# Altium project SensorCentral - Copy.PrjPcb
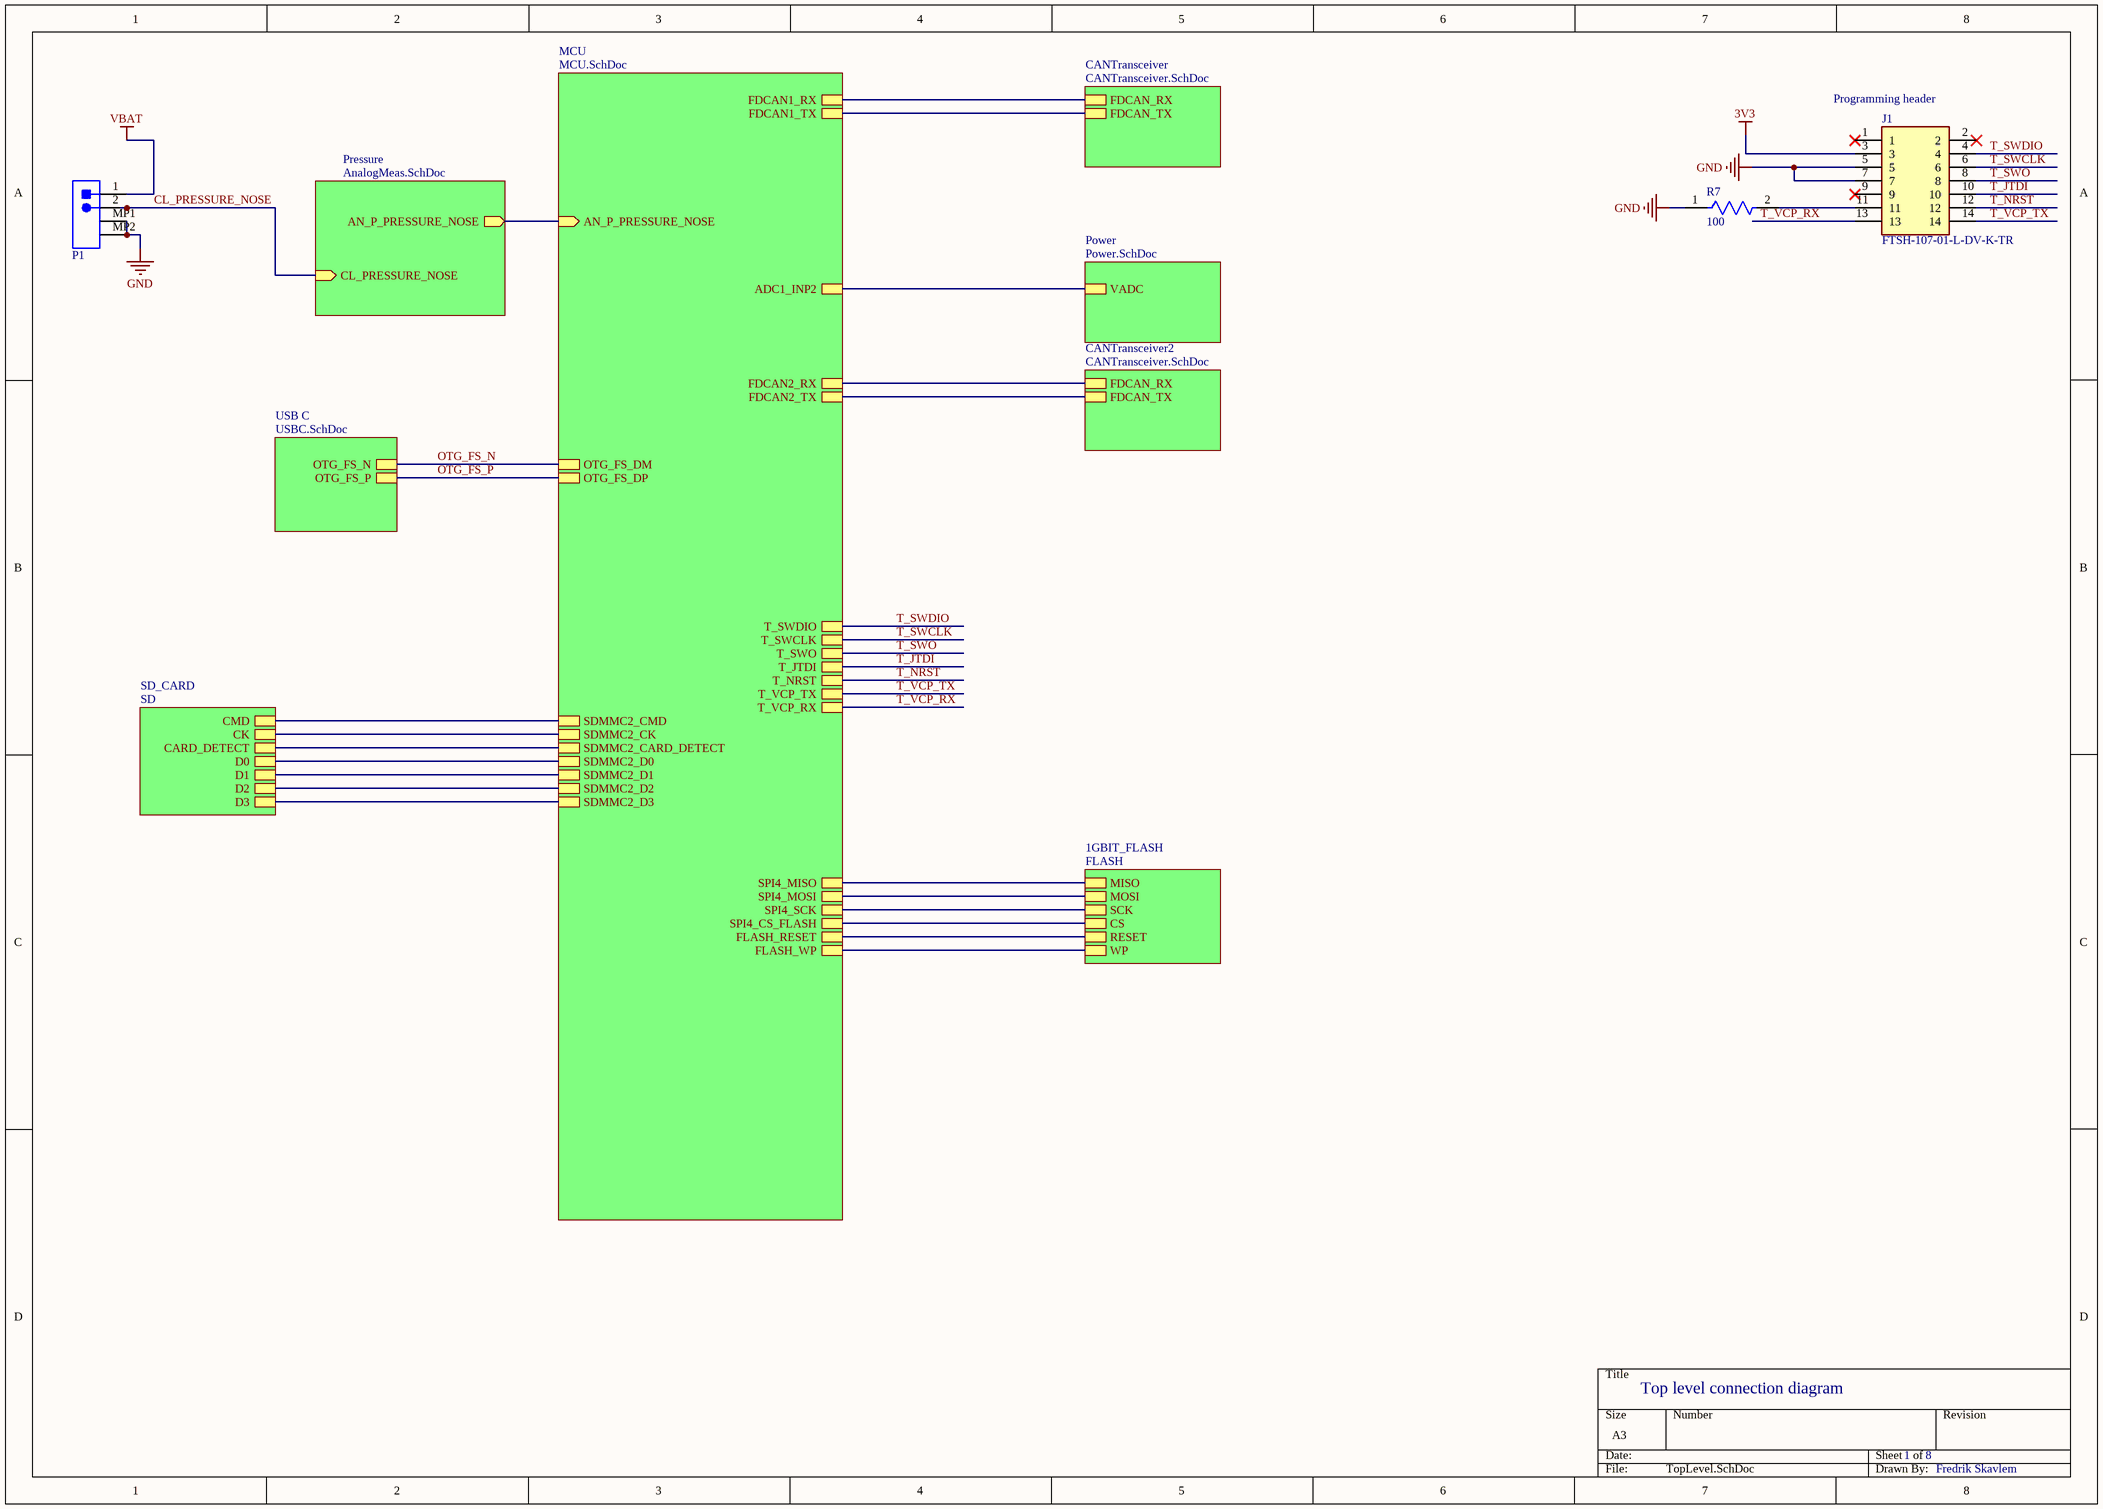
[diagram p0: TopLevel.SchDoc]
CAGE_CODE: ?????; CONTRACT_NUMBER: <CONTRACT NO>; DOC_NO_ASSY_DWG: <ASSY DWG NO>; DOC_NO_BOM: <BOM DOC NO>; DOC_NO_FAB_DWG: <FAB DWG NO>; DOC_NO_SCH_DWG: <SCH DWG NO>; PCB_2_DEC_TOL: +/-.01; PCB_3_DEC_TOL: +/-.010; PCB_ANG_TOL: +/-1/2; PCB_ASSEMBLY_NO: <PCB ASSY NO>; PCB_CHECKER: - -----; PCB_CHECKER_APP_DATE: --/--/----; PCB_DESIGNER: - -----; PCB_DESIGNER_APP_DATE: --/--/----; PCB_DWG_NO: <PCB DWG NO>; PCB_ENGINEER: - -----; PCB_ENGINEER_APP_DATE: --/--/----; PCB_PART_NUMBER: <PCB PN>; PCB_REV: A; SCH_REV: A
8 sheets, 91 parts. Net scope: hierarchical (ports join the sheet entries above them; power ports are global).
Board file: SensorCentral.PcbDoc
Sheets:
  TopLevel.SchDoc
    MCU = MCU.SchDoc
    Power = Power.SchDoc
    CANTransceiver = CANTransceiver.SchDoc
    SD_CARD = SD.SchDoc
    1GBIT_FLASH = Flash.SchDoc
    CANTransceiver2 = CANTransceiver.SchDoc
    Pressure = AnalogMeas.SchDoc
    USB C = USBC.SchDoc

## Sheet TopLevel.SchDoc
size A3; DrawnBy: Fredrik Skavlem; SheetNumber: 1; SheetTotal: 8

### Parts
J1  FTSH-107-01-L-DV-K-TR  [FTSH10701LDVKTR]
P1  S2B-PH-SM4-TB(LF)(SN)  [JST- S2B-PH-SM4-TB(LF)(SN)-2_V]  (value not drawn)
R7  100  [FP-RT0603-MFG]

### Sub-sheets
1GBIT_FLASH = FLASH: WP, RESET, CS, SCK, MOSI, MISO
CANTransceiver = CANTransceiver.SchDoc: FDCAN_RX, FDCAN_TX
CANTransceiver2 = CANTransceiver.SchDoc: FDCAN_RX, FDCAN_TX
MCU = MCU.SchDoc: FDCAN1_RX, FDCAN1_TX, T_SWDIO, T_SWCLK, T_SWO, T_JTDI, T_NRST, T_VCP_TX, T_VCP_RX, SPI4_MISO, SPI4_MOSI, SPI4_SCK, FLASH_RESET, SPI4_CS_FLASH, FLASH_WP, SDMMC2_CMD, SDMMC2_CK, SDMMC2_D0, SDMMC2_D1, SDMMC2_D2, SDMMC2_D3, SDMMC2_CARD_DETECT, ADC1_INP2, FDCAN2_RX, FDCAN2_TX, AN_P_PRESSURE_NOSE (in), OTG_FS_DM, OTG_FS_DP
Power = Power.SchDoc: VADC
Pressure = AnalogMeas.SchDoc: AN_P_PRESSURE_NOSE (out), CL_PRESSURE_NOSE (in)
SD_CARD = SD: CMD, CK, CARD_DETECT, D0, D1, D2, D3
USB C = USBC.SchDoc: OTG_FS_N, OTG_FS_P

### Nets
3V3: J1.3  [project net VDD]
GND: J1.5 J1.7 P1.MP1 P1.MP2 R7.1
VBAT: P1.1
ADC1_INP2: sheet MCU/ADC1_INP2, sheet Power/VADC
AN_P_PRESSURE_NOSE: sheet MCU/AN_P_PRESSURE_NOSE, sheet Pressure/AN_P_PRESSURE_NOSE
CARD_DETECT: sheet MCU/SDMMC2_CARD_DETECT, sheet SD_CARD/CARD_DETECT
CD/DAT3: sheet MCU/SDMMC2_D3, sheet SD_CARD/D3
CL_PRESSURE_NOSE: P1.2 ; sheet Pressure/CL_PRESSURE_NOSE
CLK: sheet MCU/SDMMC2_CK, sheet SD_CARD/CK
CMD: sheet MCU/SDMMC2_CMD, sheet SD_CARD/CMD
CS: sheet MCU/SPI4_CS_FLASH, sheet 1GBIT_FLASH/CS
DAT0: sheet MCU/SDMMC2_D0, sheet SD_CARD/D0
DAT1: sheet MCU/SDMMC2_D1, sheet SD_CARD/D1
DAT2: sheet MCU/SDMMC2_D2, sheet SD_CARD/D2
FDCAN1_RX: sheet MCU/FDCAN1_RX, sheet CANTransceiver/FDCAN_RX
FDCAN1_TX: sheet MCU/FDCAN1_TX, sheet CANTransceiver/FDCAN_TX
FDCAN2_RX: sheet MCU/FDCAN2_RX, sheet CANTransceiver2/FDCAN_RX
FDCAN2_TX: sheet MCU/FDCAN2_TX, sheet CANTransceiver2/FDCAN_TX
FLASH_RESET: sheet MCU/FLASH_RESET, sheet 1GBIT_FLASH/RESET
FLASH_WP: sheet MCU/FLASH_WP, sheet 1GBIT_FLASH/WP
MISO: sheet MCU/SPI4_MISO, sheet 1GBIT_FLASH/MISO
MOSI: sheet MCU/SPI4_MOSI, sheet 1GBIT_FLASH/MOSI
OTG_FS_N: sheet MCU/OTG_FS_DM, sheet USB C/OTG_FS_N
OTG_FS_P: sheet MCU/OTG_FS_DP, sheet USB C/OTG_FS_P
SCK: sheet MCU/SPI4_SCK, sheet 1GBIT_FLASH/SCK
T_JTDI: J1.10 ; sheet MCU/T_JTDI
T_NRST: J1.12 ; sheet MCU/T_NRST
T_SWCLK: J1.6 ; sheet MCU/T_SWCLK
T_SWDIO: J1.4 ; sheet MCU/T_SWDIO
T_SWO: J1.8 ; sheet MCU/T_SWO
T_VCP_RX: J1.13 ; sheet MCU/T_VCP_RX
T_VCP_TX: J1.14 ; sheet MCU/T_VCP_TX
NetJ1_11: J1.11 R7.2

Not connected (* = marked no-connect by the designer): J1 1* 2* 9*

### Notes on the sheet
- (near J1) Programming header
- Top level connection diagram
- 1
- 8
- Fredrik Skavlem

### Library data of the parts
J1 = FTSH-107-01-L-DV-K-TR: Connector; Manufacturer_Name: SAMTEC
P1 = CMP-002-00031-2: Male Header, Pitch 2 mm, 1 x 2 Position, Height 5.5 mm, -25 to 85 degC, RoHS, Tape and Reel; Manufacturer: JST
R7 = CMP-03412-030646-1: RT0603 100Ω 0.1W 50 ppm/°C 1.00% RT0603FRE07100RL; Manufacturer: Yageo; Manufacturer Part Number: RT0603FRE10100RL; Tolerance: 0.01; Voltage Rating: 75V

## Sheet MCU.SchDoc
size A3; ENG_APP_DATE: --/--/--; DSN_APP_DATE: --/--/--; CHK_APP_DATE: --/--/--; SheetNumber: 2; SheetTotal: 8
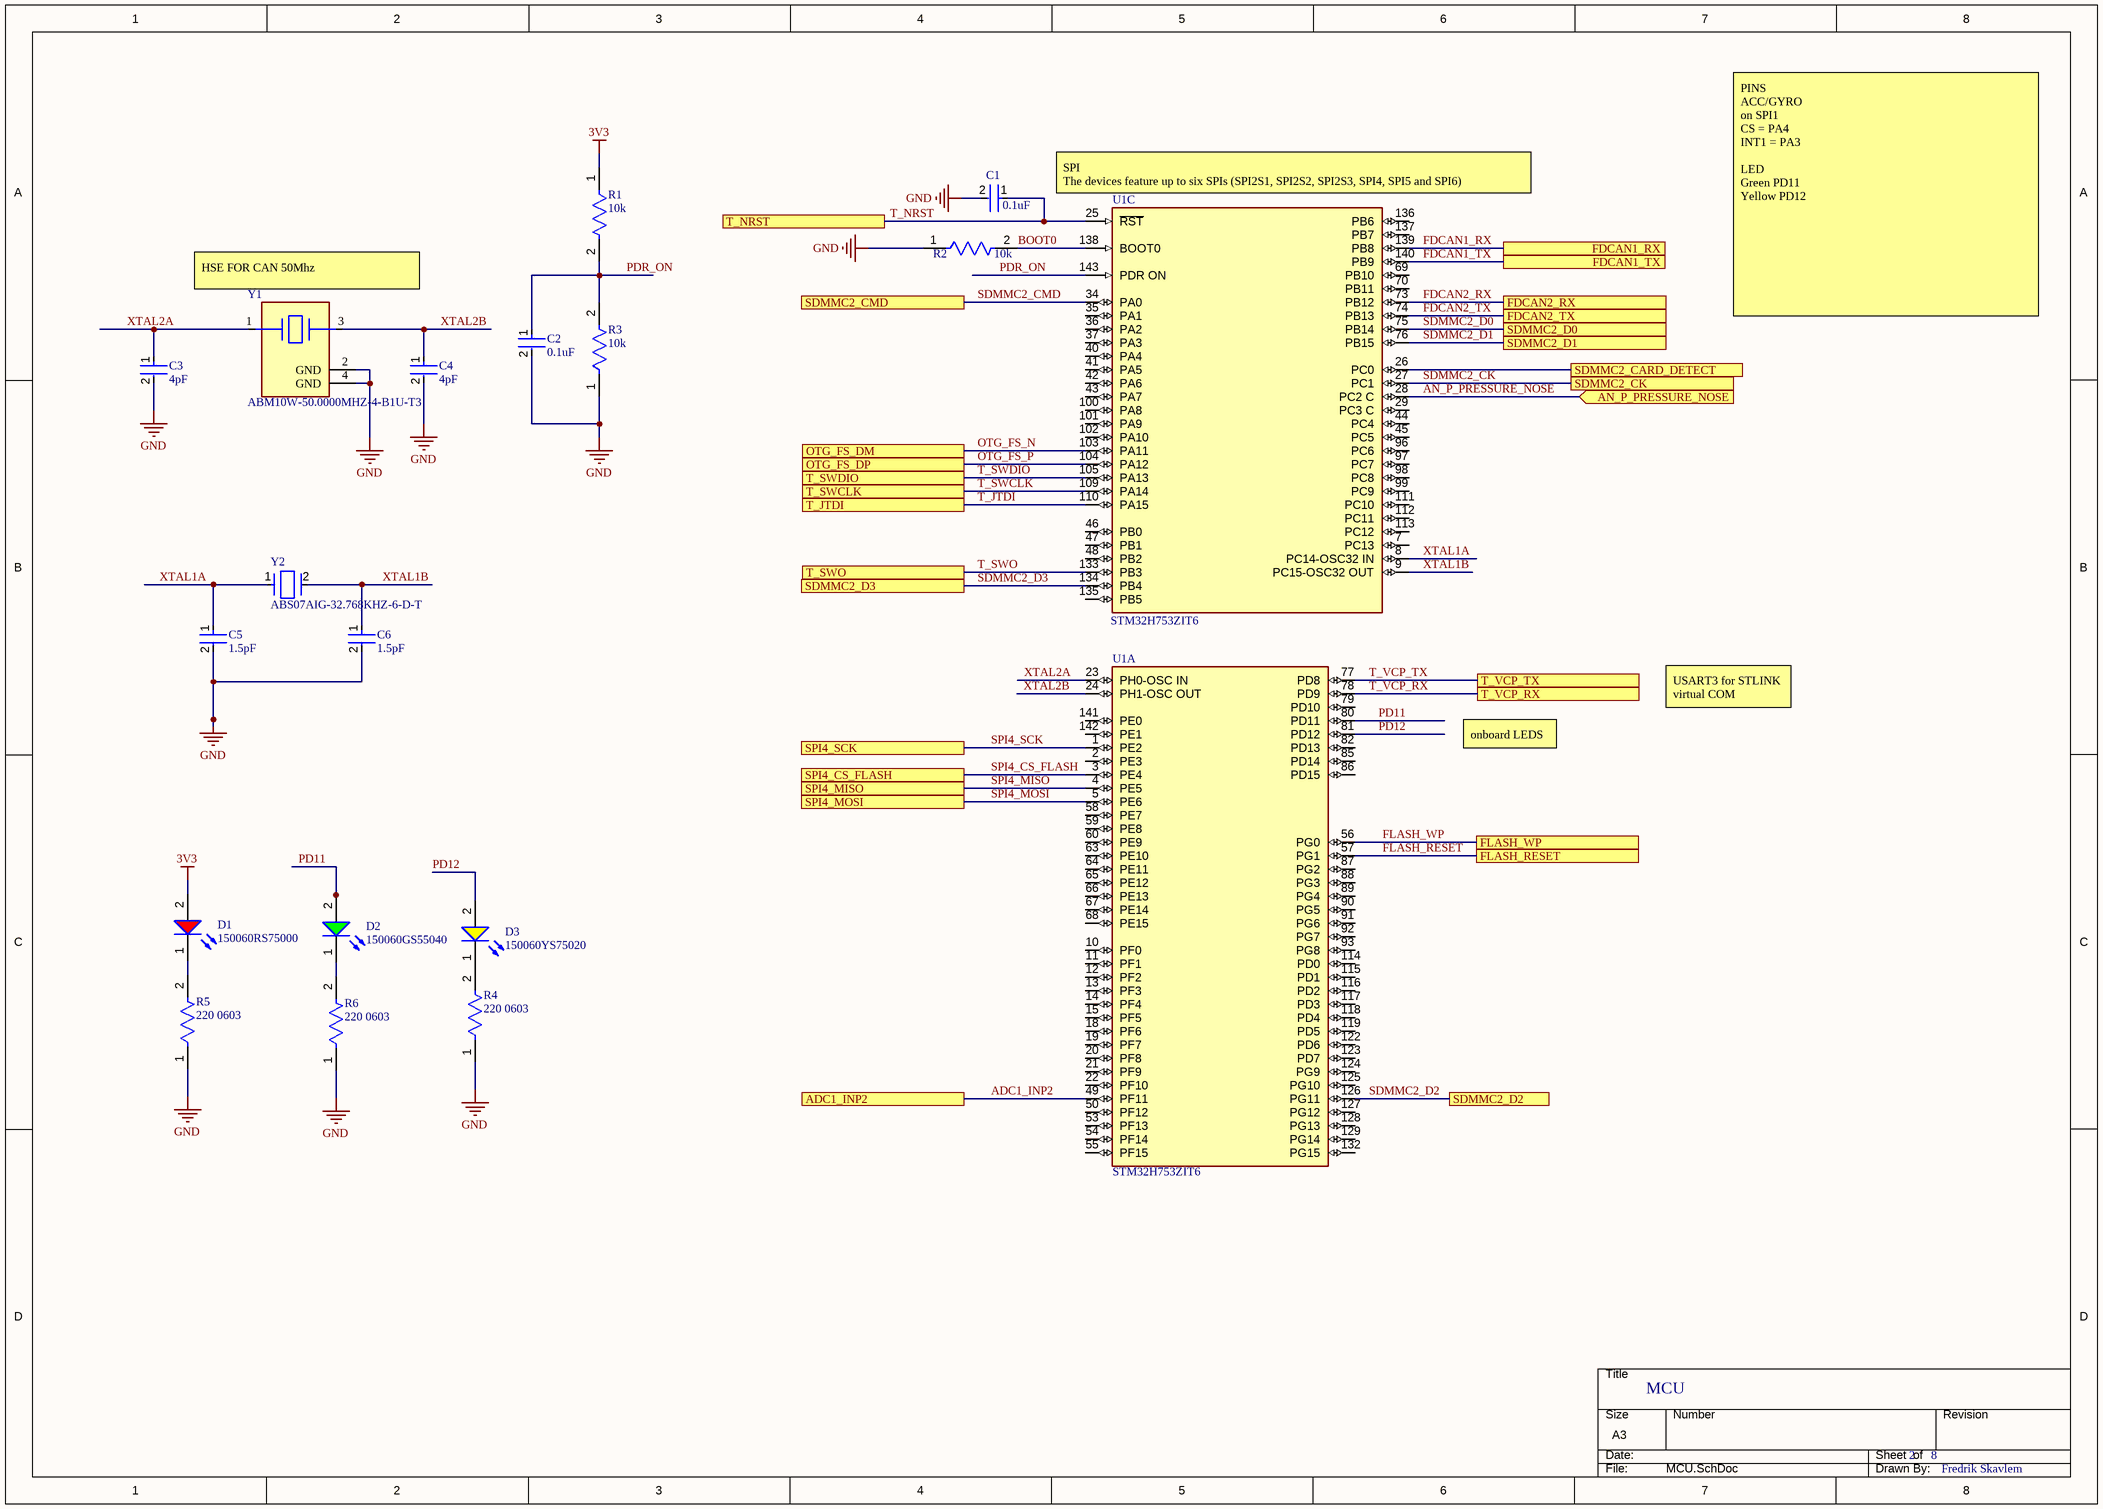
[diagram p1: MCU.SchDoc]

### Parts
C1  0.1uF  [FP-CL10-IPC_C]
C2  0.1uF  [FP-CL10-IPC_C]
C3  4pF  [FP-GQM187-0_15-IPC_B]
C4  4pF  [FP-GQM187-0_15-IPC_B]
C5  1.5pF  [FP-C0603C-CF-IPC_C]
C6  1.5pF  [FP-C0603C-CF-MFG]
D1  150060RS75000  [WL-SMCW_0603_150060xx75000]
D2  150060GS55040  [WL-SMCD_0603]
D3  150060YS75020  [WL-SMCW_0603_150060xx75020]
R1  10k  [FP-RT0603-IPC_C]
R2  10k  [FP-RT0603-IPC_C]
R3  10k  [FP-RT0603-IPC_C]
R4  220 0603  [FP-AF0603-IPC_C]
R5  220 0603  [FP-AF0603-IPC_C]
R6  220 0603  [FP-AF0603-IPC_C]
U1  STM32H753ZIT6  [FP-LQFP144-1A-MFG]  (parts A,C of 3)
Y1  ABM10W-50.0000MHZ-4-B1U-T3  [FP-ABM10W-MFG]
Y2  ABS07AIG-32.768KHZ-6-D-T  [FP-ABS07AIG-MFG]

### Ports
ADC1_INP2, AN_P_PRESSURE_NOSE (in), FDCAN1_RX, FDCAN1_TX, FDCAN2_RX, FDCAN2_TX, FLASH_RESET, FLASH_WP, OTG_FS_DM, OTG_FS_DP, SDMMC2_CARD_DETECT, SDMMC2_CK, SDMMC2_CMD, SDMMC2_D0, SDMMC2_D1, SDMMC2_D2, SDMMC2_D3, SPI4_CS_FLASH, SPI4_MISO, SPI4_MOSI, SPI4_SCK, T_JTDI, T_NRST, T_SWCLK, T_SWDIO, T_SWO, T_VCP_RX, T_VCP_TX

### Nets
3V3: D1.2(A) R1.1  [project net VDD]
GND: C1.2 C2.2 C3.2 C4.2 C5.2 C6.2 R2.1 R3.1 R4.1 R5.1 R6.1 Y1.2(GND) Y1.4(GND)
ADC1_INP2: U1.49(PF11) ; port ADC1_INP2
AN_P_PRESSURE_NOSE: U1.28(PC2_C) ; port AN_P_PRESSURE_NOSE
BOOT0: R2.2 U1.138(BOOT0)
CARD_DETECT: U1.26(PC0) ; port SDMMC2_CARD_DETECT
FDCAN1_RX: U1.139(PB8) ; port FDCAN1_RX
FDCAN1_TX: U1.140(PB9) ; port FDCAN1_TX
FDCAN2_RX: U1.73(PB12) ; port FDCAN2_RX
FDCAN2_TX: U1.74(PB13) ; port FDCAN2_TX
FLASH_RESET: U1.57(PG1) ; port FLASH_RESET
FLASH_WP: U1.56(PG0) ; port FLASH_WP
OTG_FS_N: U1.103(PA11) ; port OTG_FS_DM
OTG_FS_P: U1.104(PA12) ; port OTG_FS_DP
PD11: D2.2(A) U1.80(PD11)
PD12: D3.2(A) U1.81(PD12)
PDR_ON: C2.1 R1.2 R3.2 U1.143(PDR_ON)
SDMMC2_CK: U1.27(PC1) ; port SDMMC2_CK  [project net CLK]
SDMMC2_CMD: U1.34(PA0) ; port SDMMC2_CMD  [project net CMD]
SDMMC2_D0: U1.75(PB14) ; port SDMMC2_D0  [project net DAT0]
SDMMC2_D1: U1.76(PB15) ; port SDMMC2_D1  [project net DAT1]
SDMMC2_D2: U1.126(PG11) ; port SDMMC2_D2  [project net DAT2]
SDMMC2_D3: U1.134(PB4) ; port SDMMC2_D3  [project net CD/DAT3]
SPI4_CS_FLASH: U1.3(PE4) ; port SPI4_CS_FLASH  [project net CS]
SPI4_MISO: U1.4(PE5) ; port SPI4_MISO  [project net MISO]
SPI4_MOSI: U1.5(PE6) ; port SPI4_MOSI  [project net MOSI]
SPI4_SCK: U1.1(PE2) ; port SPI4_SCK  [project net SCK]
T_JTDI: U1.110(PA15) ; port T_JTDI
T_NRST: C1.1 U1.25(~{RST}) ; port T_NRST
T_SWCLK: U1.109(PA14) ; port T_SWCLK
T_SWDIO: U1.105(PA13) ; port T_SWDIO
T_SWO: U1.133(PB3) ; port T_SWO
T_VCP_RX: U1.78(PD9) ; port T_VCP_RX
T_VCP_TX: U1.77(PD8) ; port T_VCP_TX
XTAL1A: C5.1 U1.8(PC14-OSC32_IN) Y2.1
XTAL1B: C6.1 U1.9(PC15-OSC32_OUT) Y2.2
XTAL2A: C3.1 U1.23(PH0-OSC_IN) Y1.1
XTAL2B: C4.1 U1.24(PH1-OSC_OUT) Y1.3
NetD1_1: D1.1(K) R5.2
NetD2_1: D2.1(K) R6.2
NetD3_1: D3.1(K) R4.2

Not connected (* = marked no-connect by the designer): U1 2(PE3) 7(PC13) 10(PF0) 11(PF1) 12(PF2) 13(PF3) 14(PF4) 15(PF5) 18(PF6) 19(PF7) 20(PF8) 21(PF9) 22(PF10) 29(PC3_C) 35(PA1) 36(PA2) 37(PA3) 40(PA4) 41(PA5) 42(PA6) 43(PA7) 44(PC4) 45(PC5) 46(PB0) 47(PB1) 48(PB2) 50(PF12) 53(PF13) 54(PF14) 55(PF15) 58(PE7) 59(PE8) 60(PE9) 63(PE10) 64(PE11) 65(PE12) 66(PE13) 67(PE14) 68(PE15) 69(PB10) 70(PB11) 79(PD10) 82(PD13) 85(PD14) 86(PD15) 87(PG2) 88(PG3) 89(PG4) 90(PG5) 91(PG6) 92(PG7) 93(PG8) 96(PC6) 97(PC7) 98(PC8) 99(PC9) 100(PA8) 101(PA9) 102(PA10) 111(PC10) 112(PC11) 113(PC12) 114(PD0) 115(PD1) 116(PD2) 117(PD3) 118(PD4) 119(PD5) 122(PD6) 123(PD7) 124(PG9) 125(PG10) 127(PG12) 128(PG13) 129(PG14) 132(PG15) 135(PB5) 136(PB6) 137(PB7) 141(PE0) 142(PE1)

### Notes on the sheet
- (near U1) SPI
  The devices feature up to six SPIs (SPI2S1, SPI2S2, SPI2S3, SPI4, SPI5 and SPI6)
- (near Y1) HSE FOR CAN 50Mhz
- PINS
  ACC/GYRO
  on SPI1
  CS = PA4
  INT1 = PA3
  LED
  Green PD11
  Yellow PD12
- USART3 for STLINK virtual COM
- onboard LEDS
- MCU
- 2
- 8
- Fredrik Skavlem

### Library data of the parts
C1 C2 = CMP-13271-002683-1: Cap Ceramic 100nF 16V X7R ±10% Pad SMD 0603 +125°C T/R / CL10B104KO8WPNC
C3 C4 = CMP-06035-061124-1: GQM1875C2E4R0BB12D / Ceramic Capacitor 4pF ±0.1pF 250VDC C0G 0603 Paper T/R; Voltage Rating: 250V
C5 C6 = CMP-03020-023157-1: C0603 1.5 pF X8R 30ppm/°C 0.1 pF 25 V / C0603C159B3HACTU; Manufacturer: KEMET; Automotive Grade: Grade 1; Material: Ceramic; Tolerance: 0.1 pF; Voltage Rating: 25 V
D1 = CMP-1426-00001-3: NexarPartId: 29717776; Color: Red; Power Dissipation: 72mW; Max Reverse Voltage (DC): 5V; Peak Wavelength: 630nm; Viewing Angle: 140°; Forward Voltage: 2V; Luminous Intensity: 250mcd; Forward Current: 100mA; Dominant Wavelength: 625nm; Lens Style: Clear, Rectangular; Max Junction Temperature (Tj): 95°C; Test Current: 20mA
D2 = CMP-03913-90235563-2: 150060GS55040 WL-SMCD SMT Mono-color Chip LED Diffused; Forward Voltage: 3.2V; Forward Current: 60mA; Luminous Intensity: 430mcd; Peak Wavelength: 520nm; Viewing Angle: 140°; Wavelength: 525nm; Max Reverse Voltage (DC): 5V
D3 = CMP-03913-104891429-2: WL-SMCW SMT Mono-Color Chip LED Waterclear super f; Forward Voltage: 2V; Forward Current: 60mA; Max Reverse Voltage (DC): 5V; Peak Wavelength: 595nm; Viewing Angle: 140°; Dominant Wavelength: 590nm; Luminous Intensity: 130mcd
R1-R3 = CMP-03412-005349-1: RES SMD 10K OHM 1% 1/10W 0603 / RT0603FRE0710KL; Manufacturer: Yageo; Value: 10KΩ; Temperature Coefficient: 50 ppm/°C; Power Rating: 0.1W; Tolerance: 0.01; Voltage Rating: 75V
R4-R6 = CMP-03412-038529-1: AF0603JR-07220RL Anti-Sulfurated Chip Resistors Automotive Grade 220Ω 5% 100ppm/°C 0603; Max Power Dissipation: 100mW; Resistance: 220R
U1 = CMP-12105-000009-1: LQFP 144 20X20X1.4 2; Manufacturer: STMicroelectronics; Number Of Pwm Channels: 24; Number Of I/Os: 114; Number Of Cores: 1; Min Supply Voltage: 1.62V; Interface: I2C,SPI,UART,USART,CAN,USB,LIN,IrDA,Ethernet,I2S,SMBus,Other; Standoff Height: 0.05mm; Number Of I2C Channels: 4; Max Junction Temp: +125°C; Memory Type: FLASH; Ram Size: 1MBytes; Number Of Spi Channels: 6; Core Architecture: ARM Cortex-M7; Number Of Uart Channels: 9; Memory Size: 2MBytes; Number Of Adc Channels: 36; Frequency: 480MHz; Data Bus Width: 32bits; Max Supply Voltage: 3.6V; Number Of Usb Channels: 2; Number Of A/D Converters: 3; Number Of Timers/Counters: 20
Y1 = CMP-27762-007472-1: Crystal 50MHz ±10ppm 4pF SMD-4 2.5mm x 2mm; ESR (Equivalent Series Resistance): 70R
Y2 = CMP-27762-015953-1: Crystal 32.768kHz ±20ppm (Tol) 6pF FUND 70kΩ Automotive 2-Pin Mini-CSMD T/R; ESR (Equivalent Series Resistance): 70kR

## Sheet Power.SchDoc
size A3; SheetNumber: 4; SheetTotal: 8
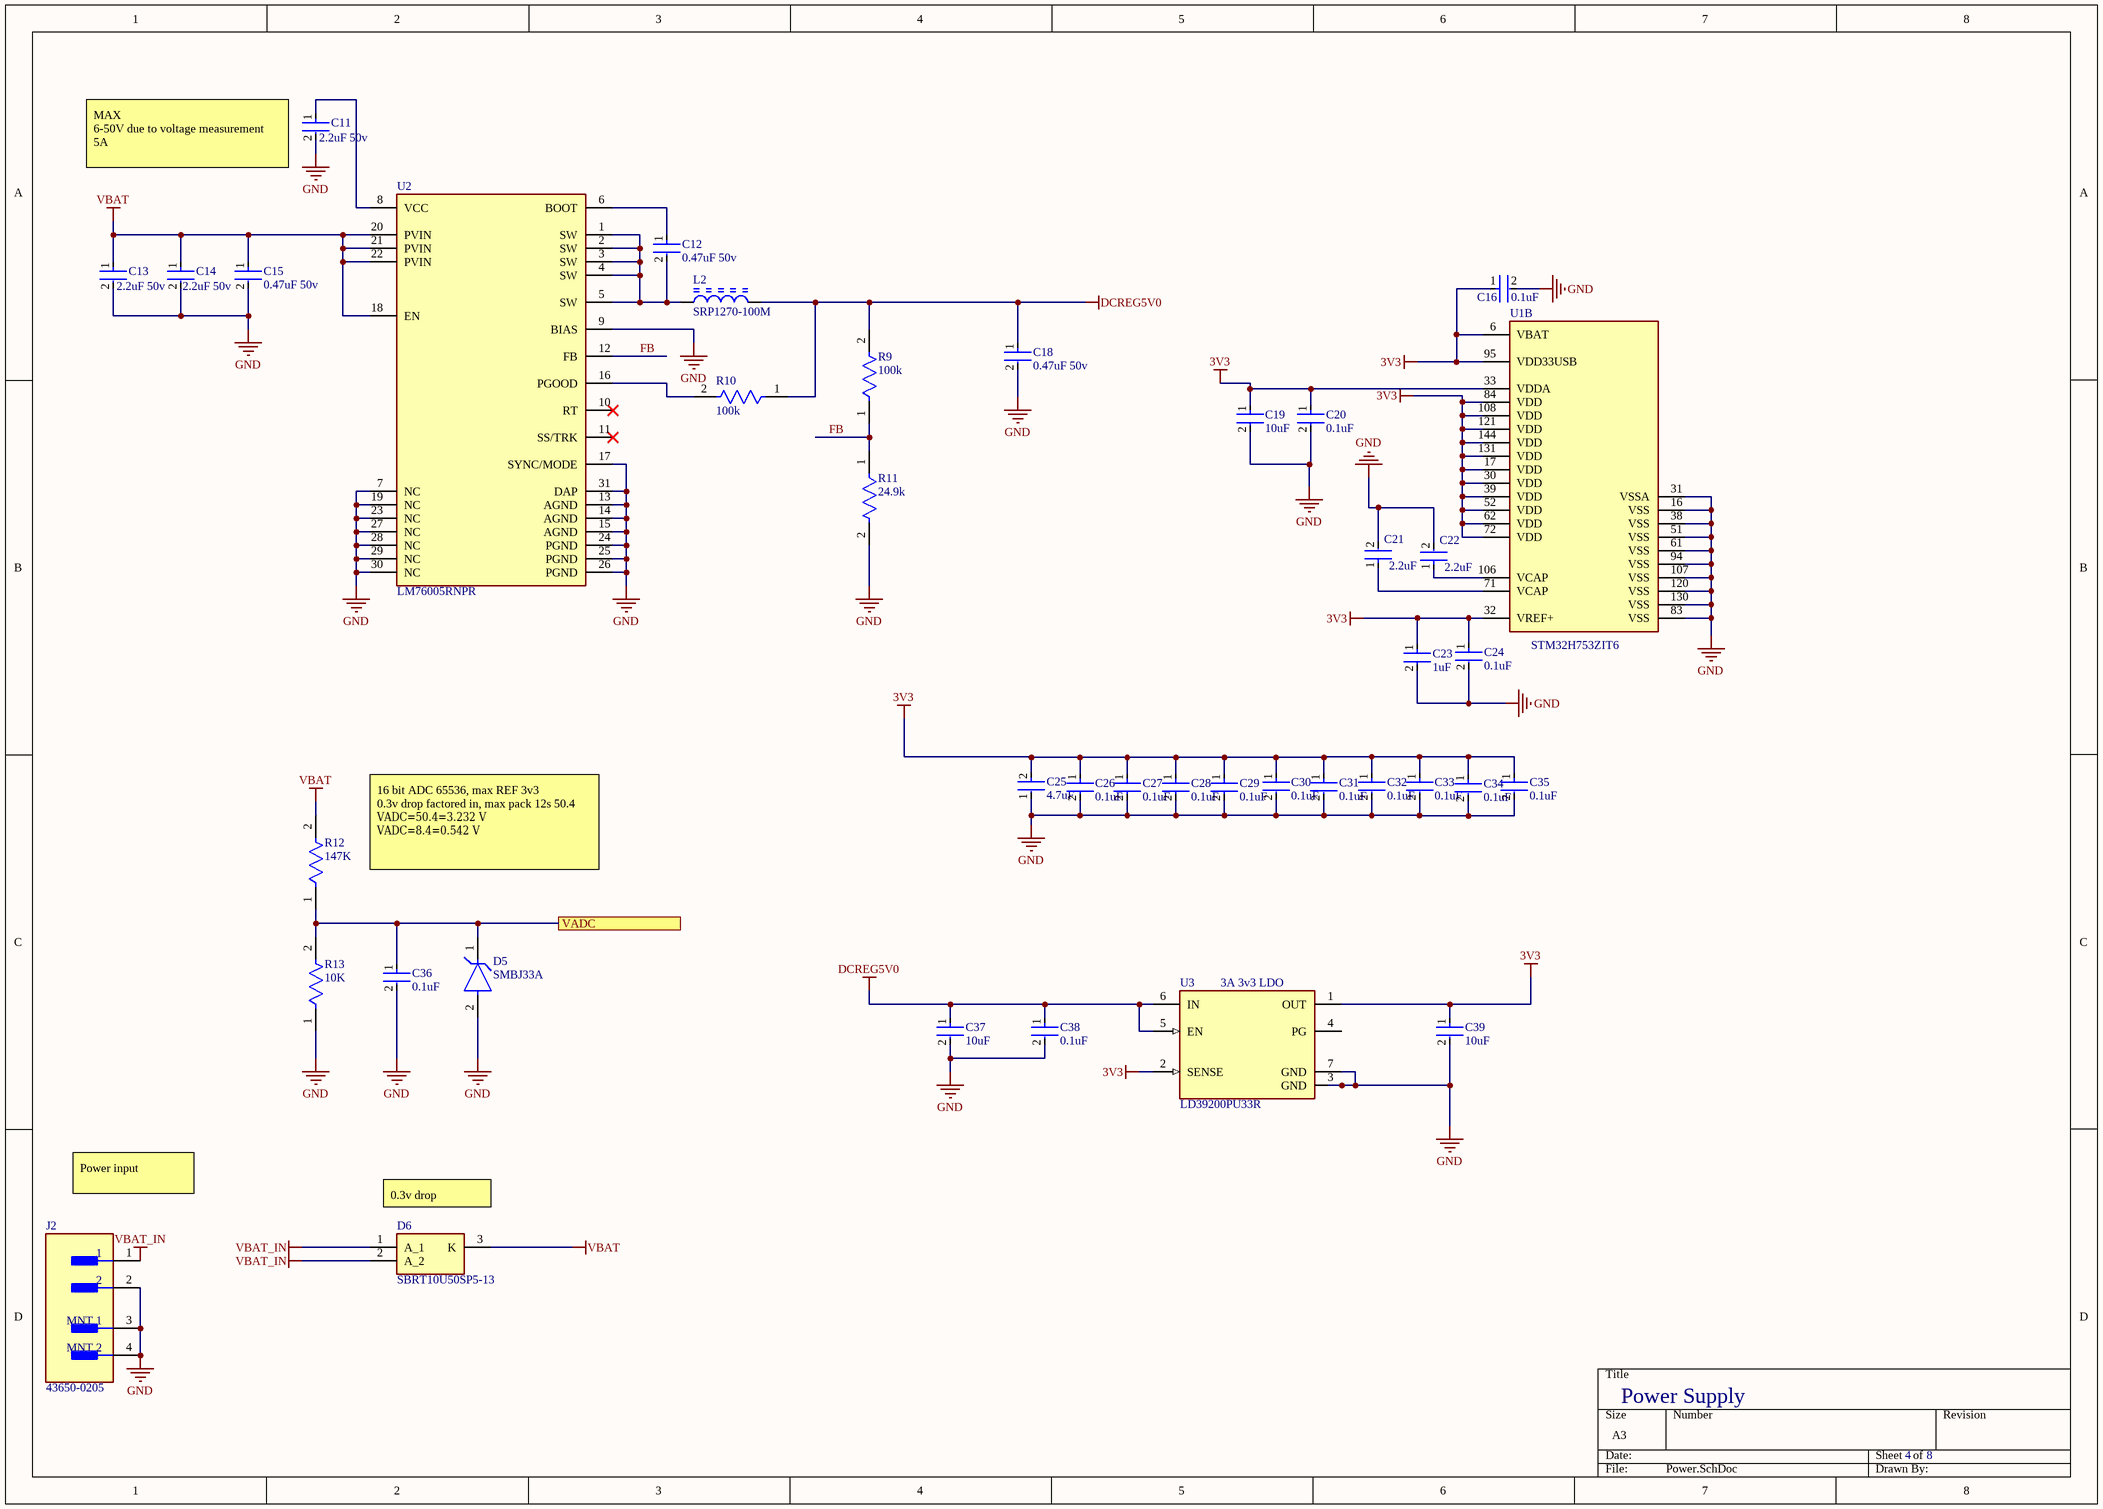
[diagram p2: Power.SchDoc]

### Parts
C11  2.2uF 50v  [FP-GRM188-0_2-IPC_C]
C12  0.47uF 50v  [FP-0603-L_1_6_0_15-W_0_8-MFG]
C13  2.2uF 50v  [FP-GRM188-0_2-IPC_C]
C14  2.2uF 50v  [FP-GRM188-0_2-IPC_C]
C15  0.47uF 50v  [FP-0603-L_1_6_0_15-W_0_8-MFG]
C16  0.1uF  [FP-CL10-IPC_C]
C18  0.47uF 50v  [FP-0603-L_1_6_0_15-W_0_8-MFG]
C19  10uF  [FP-CL10-IPC_C]
C20  0.1uF  [FP-CL10-IPC_C]
C21  2.2uF  [FP-CL10-IPC_C]
C22  2.2uF  [FP-CL10-IPC_C]
C23  1uF  [FP-CL10-IPC_C]
C24  0.1uF  [FP-CL10-IPC_C]
C25  4.7uF  [FP-C1608-080-0_1-MFG]
C26  0.1uF  [FP-CL10-IPC_C]
C27  0.1uF  [FP-CL10-IPC_C]
C28  0.1uF  [FP-CL10-IPC_C]
C29  0.1uF  [FP-CL10-IPC_C]
C30  0.1uF  [FP-CL10-IPC_C]
C31  0.1uF  [FP-CL10-IPC_C]
C32  0.1uF  [FP-CL10-IPC_C]
C33  0.1uF  [FP-CL10-IPC_C]
C34  0.1uF  [FP-CL10-IPC_C]
C35  0.1uF  [FP-CL10-IPC_C]
C36  0.1uF  [FP-CL10-IPC_C]
C37  10uF  [FP-CL10-IPC_C]
C38  0.1uF  [FP-CL10-IPC_C]
C39  10uF  [FP-CL10-IPC_C]
D5  SMBJ33A  [FP-SMBJ-MFG]
D6  SBRT10U50SP5-13  [SBRT10U50SP513]
J2  43650-0205  [FP-43650-0205-MFG]
L2  SRP1270-100M  [BOUR-SRP1270-100M-2_V]
R9  100k  [FP-RC0603-0_55-IPC_C]
R10  100k  [FP-RC0603-0_55-IPC_C]
R11  24.9k  [FP-RG1608-IPC_C]
R12  147K  [FP-RT0603-MFG]
R13  10K  [FP-ERJPB3-IPC_C]
U1  STM32H753ZIT6  [FP-LQFP144-1A-MFG]  (part B of 3)
U2  LM76005RNPR  [FP-RNP0030A-MFG]
U3  LD39200PU33R  [FP-DFN6-7946637-MFG]

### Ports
VADC

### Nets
3V3: C16.1 C19.1 C20.1 C23.1 C24.1 C25.2 C26.1 C27.1 C28.1 C29.1 C30.1 C31.1 C32.1 C33.1 C34.1 C35.1 C39.1 U1.6(VBAT) U1.17(VDD) U1.30(VDD) U1.32(VREF+) U1.33(VDDA) U1.39(VDD) U1.52(VDD) U1.62(VDD) U1.72(VDD) U1.84(VDD) U1.95(VDD33USB) U1.108(VDD) U1.121(VDD) U1.131(VDD) U1.144(VDD) U3.1(OUT) U3.2(SENSE)  [project net VDD]
DCREG5V0: C18.1 C37.1 C38.1 L2.2 R9.2 R10.1 U3.5(EN) U3.6(IN)
GND: C11.2 C13.2 C14.2 C15.2 C16.2 C18.2 C19.2 C20.2 C21.2 C22.2 C23.2 C24.2 C25.1 C26.2 C27.2 C28.2 C29.2 C30.2 C31.2 C32.2 C33.2 C34.2 C35.2 C36.2 C37.2 C38.2 C39.2 D5.2(A) J2.2 J2.3(MNT_1) J2.4(MNT_2) R11.2 R13.1 U1.16(VSS) U1.31(VSSA) U1.38(VSS) U1.51(VSS) U1.61(VSS) U1.83(VSS) U1.94(VSS) U1.107(VSS) U1.120(VSS) U1.130(VSS) U2.7(NC) U2.9(BIAS) U2.13(AGND) U2.14(AGND) U2.15(AGND) U2.17(SYNC/MODE) U2.19(NC) U2.23(NC) U2.24(PGND) U2.25(PGND) U2.26(PGND) U2.27(NC) U2.28(NC) U2.29(NC) U2.30(NC) U2.31(DAP) U3.3(GND) U3.7(GND)
VBAT: C13.1 C14.1 C15.1 D6.3(K) R12.2 U2.18(EN) U2.20(PVIN) U2.21(PVIN) U2.22(PVIN)
VBAT_IN: D6.1(A_1) D6.2(A_2) J2.1
ADC1_INP2: C36.1 D5.1(C) R12.1 R13.2 ; port VADC
FB: R9.1 R11.1 U2.12(FB)
NetC11_1: C11.1 U2.8(VCC)
NetC12_1: C12.1 U2.6(BOOT)
NetC12_2: C12.2 L2.1 U2.1(SW) U2.2(SW) U2.3(SW) U2.4(SW) U2.5(SW)
NetC21_1: C21.1 U1.71(VCAP)
NetC22_1: C22.1 U1.106(VCAP)
NetR10_2: R10.2 U2.16(PGOOD)

Not connected (* = marked no-connect by the designer): U2 10(RT)* 11(SS/TRK)*; U3 4(PG)

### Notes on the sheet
- (near C11) MAX
  6-50V due to voltage measurement
  5A
- 16 bit ADC 65536, max REF 3v3
  0.3v drop factored in, max pack 12s 50.4
  VADC​=50.4=3.232 V
  VADC​=8.4=0.542 V
- (near U3) 3A 3v3 LDO
- Power input
- (near D6) 0.3v drop
- Power Supply
- 4
- 8

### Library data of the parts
C11 C13 C14 = CMP-06035-043613-1: GRM188R61H225ME11J Chip Multilayer Ceramic Capacitors for General Purpose, 0603, 2.2uF, X5R, 15%, 20%, 50V
C12 C15 C18 = CMP-14477-000175-2: UMK107ABJ474KA-T; Tolerance: 10%; Dielectric: X5R; Capacitance: 470nF
C16 C20 C24 C26-C36 C38 = CMP-13271-002683-1: as C1 on sheet MCU
C19 C37 C39 = CMP-13271-003287-1: Cap Ceramic 10uF 16V X6S ±20% Pad SMD 0603 +105°C T/R / CL10X106MO8NRNC
C21 C22 = CMP-13271-003360-1: Cap Ceramic 2.2uF 16V X5R ±10% Pad SMD 0603 +85°C T/R / CL10A225KO8NNND; Capacitance: 2.2nF
C23 = CMP-13271-000784-1: Cap Ceramic 1uF 16V X7R ±10% Pad SMD 0603 +125°C T/R / CL10B105KO8NNNL
C25 = CMP-08246-005518-1: Multilayer Ceramic Capacitors 4.7μF ±10% 25V X5R SMD 0603 / C1608X5R1E475K080AC
D5 = CMP-2000-07095-2: TVS DIODE 33V 53.3V DO214AA; Manufacturer: Littelfuse Inc; Max Junction Temp: +150°C; Number Of Channels: 1; Breakdown Voltage: 36.7V; Peak Pulse Power: 600W; Direction: Unidirectional; Peak Pulse Current: 11.3A
D6 = SBRT10U50SP5-13: Diode; Manufacturer_Name: Diodes Incorporated
J2 = CMP-00257-07672643-1: 43650-0205 Conn Wire to Board HDR 2 POS 3mm Solder RA Side Entry Thru-Hole Micro-Fit 3.0™ Tray; Manufacturer Lifecycle Status: ACTIVE; Plating: Tin; Glow Wire Compliant: Compliant; Number of Contacts: 2; Gender: Male; Voltage Rating: 600V; Current Rating: 5A
L2 = CMP-2000-05082-1: Shielded Power Inductor, 10 uH, +/- 20%, 10 A, -55 to 125 degC, 2-Pin SMD, RoHS, Tape and Reel; Manufacturer: Bourns; Type: Wirewound; Material - Core: Iron; 3D Model: SRP1270.stp; EDA / CAD Models: DownloadfromAcceleratedDesigns; Other Names: SRP1270-100M-ND / SRP1270-100MTR / SRP1270100M; Online Catalog: SRPSeries; Frequency - Test: 100kHz; Inductance: 10µH; DC Resistance (DCR): 16.8mOhmMax; Current Rating: 10A; Current - Saturation: 16A; Frequency - Self Resonant: 10MHz
R9 R10 = CMP-2100-03662-2: RC0603FR-07100KL RES SMD 100K OHM 1% 1/10W 0603; Voltage Rating (DC): 50V; Resistance: 100kR; Max Power Dissipation: 100mW; Temperature Coefficient: 100ppm/°C; Working Voltage: 75V
R11 = CMP-2000-02140-2: RG1608P-2492-B-T5 / Automotive Metal Thin Film Chip Resistor, 0603, 24.9kΩ, 0.1%, 25ppm/°C, 0.1W, 100V; Power Rating: 100mW; Resistance: 24.9kR; Voltage Rating (DC): 75V
R12 = CMP-03412-029582-1: RT0603BRD07147KL / RES SMD 147K OHM 0.1% 1/10W 0603; Manufacturer: Yageo; Value: 147KΩ; Tolerance: 0.001; Temperature Coefficient: 25 ppm/°C; Power Rating: 0.1W; Voltage Rating: 75V
R13 = CMP-05422-000107-1: ERJ-PB3B1002V / RES SMD 10K OHM 0.1% 1/5W 0603; Max Power Dissipation: 200mW; Temperature Coefficient: 50ppm/°C; Resistance: 10kR
U1 = CMP-12105-000009-1: as U1 on sheet MCU
U2 = CMP-04918-000213-1: 3.5-V TO 60-V, 5-A SYNCHRONOUS S
U3 = CMP-12153-000011-1: IC REG LINEAR 3.3V 2A 6DFN; Number of Outputs: 1; Max Input Voltage: 6V; Output Type: Fixed; Min Input Voltage: 1.25V; Dropout Voltage: 130mV; Operating Supply Current: 1mA

## Sheet CANTransceiver.SchDoc
size A4; SheetNumber: 5; SheetTotal: 8
Used 2 times, as channels CANTransceiver, CANTransceiver2. Parts and nets are listed once, with the designators drawn on the sheet.
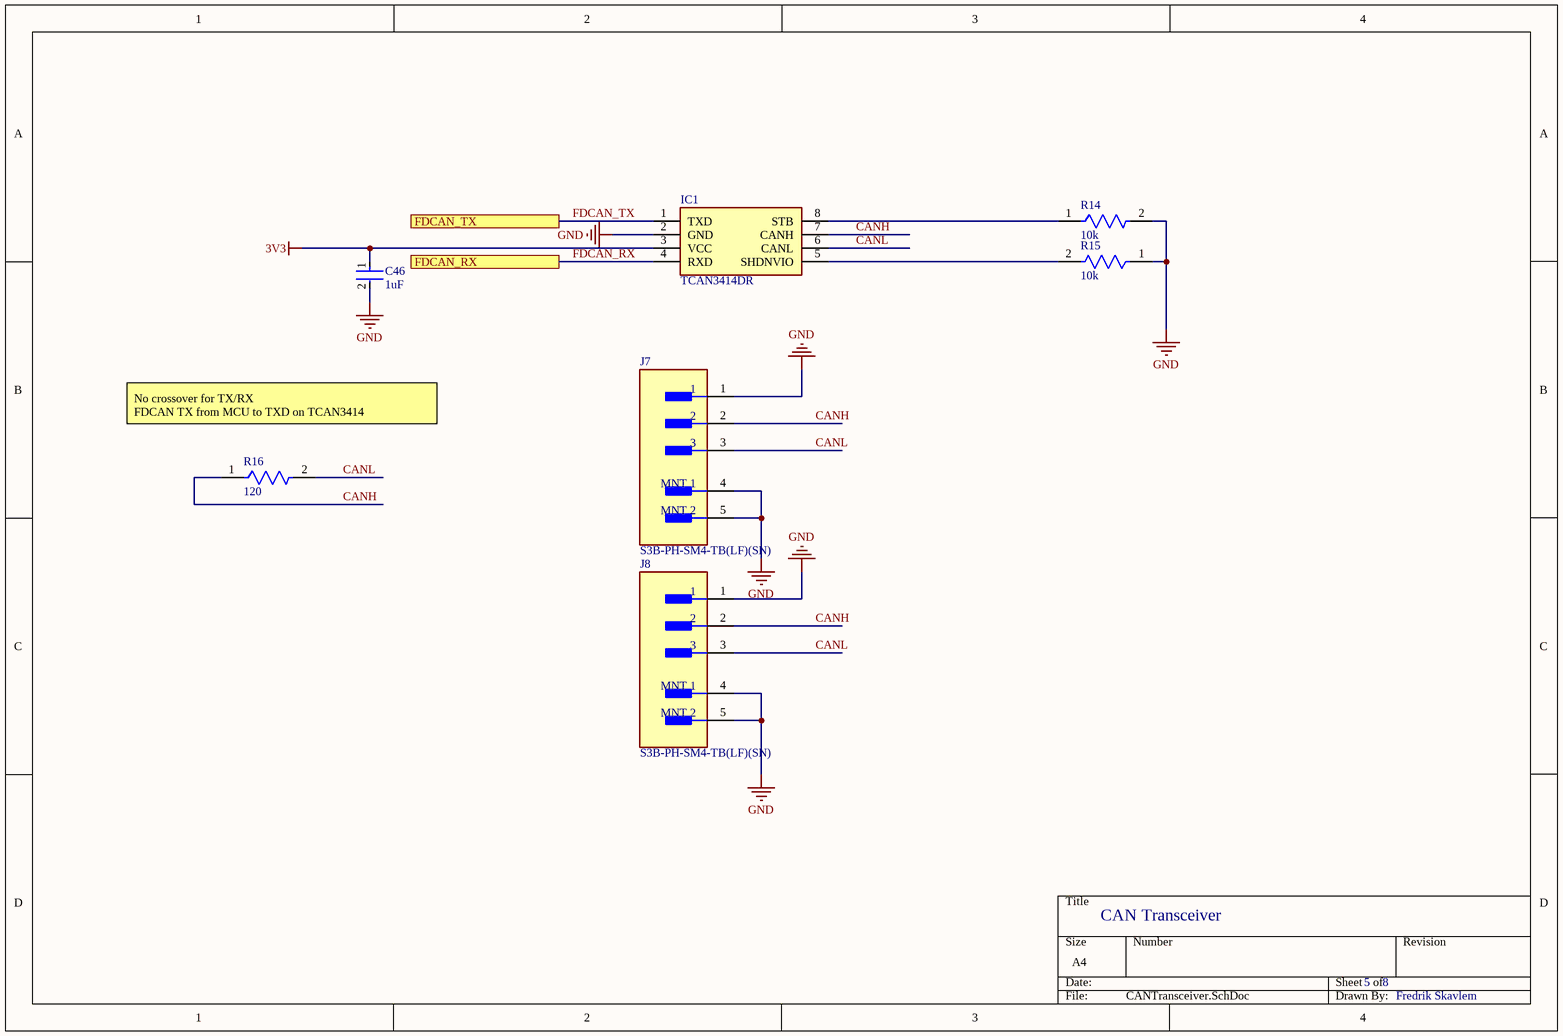
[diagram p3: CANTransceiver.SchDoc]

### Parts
C46  1uF  [FP-CL10-IPC_C]
IC1  TCAN3414DR  [SOIC127P600X175-8N]
J7  S3B-PH-SM4-TB(LF)(SN)  [FP-S3B-PH-SM4-TB_LF_SN-MFG]
J8  S3B-PH-SM4-TB(LF)(SN)  [FP-S3B-PH-SM4-TB_LF_SN-MFG]
R14  10k  [FP-RT0603-IPC_C]
R15  10k  [FP-RT0603-IPC_C]
R16  120  [FP-AF0603-IPC_C]

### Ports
FDCAN_RX, FDCAN_TX

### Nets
3V3: C46.1 IC1.3(VCC)
GND: C46.2 IC1.2(GND) J7.1 J7.4(MNT_1) J7.5(MNT_2) J8.1 J8.4(MNT_1) J8.5(MNT_2) R14.2 R15.1
CANH: IC1.7(CANH) J7.2 J8.2 R16.1
CANL: IC1.6(CANL) J7.3 J8.3 R16.2
FDCAN_RX: IC1.4(RXD) ; port FDCAN_RX
FDCAN_TX: IC1.1(TXD) ; port FDCAN_TX
NetIC1_5: IC1.5(SHDNVIO) R15.2
NetIC1_8: IC1.8(STB) R14.1

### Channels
CANTransceiver: designators end in _CANTransceiver; ports FDCAN_RX=FDCAN1_RX FDCAN_TX=FDCAN1_TX
CANTransceiver2: designators end in _CANTransceiver2; ports FDCAN_RX=FDCAN2_RX FDCAN_TX=FDCAN2_TX

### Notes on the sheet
- No crossover for TX/RX
  FDCAN TX from MCU to TXD on TCAN3414
- CAN Transceiver
- 5
- 8
- Fredrik Skavlem

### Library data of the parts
C46 = CMP-13271-000784-1: as C23 on sheet Power
IC1 = TCAN3414DR: Integrated Circuit; Manufacturer_Name: Texas Instruments
J7 J8 = CMP-002-00113-1: Connector Header, PH Series, 3 Position, Side Entry, 2.00mm, Solder, Surface Mount, Natural.; Voltage Rating: 100V; Max Current Rating: 2A; Connector Type: Male Pin; Gender: Male
R14 R15 = CMP-03412-005349-1: as R1 on sheet MCU
R16 = CMP-03412-039700-1: Anti-Sulfurated Chip Resistors Automotive Grade 120Ω 1% 100ppm/°C 0603 AF0603FR-07120RL; Max Power Dissipation: 100mW; Resistance: 120R

## Sheet SD.SchDoc
size A4; SheetNumber: 7; SheetTotal: 8
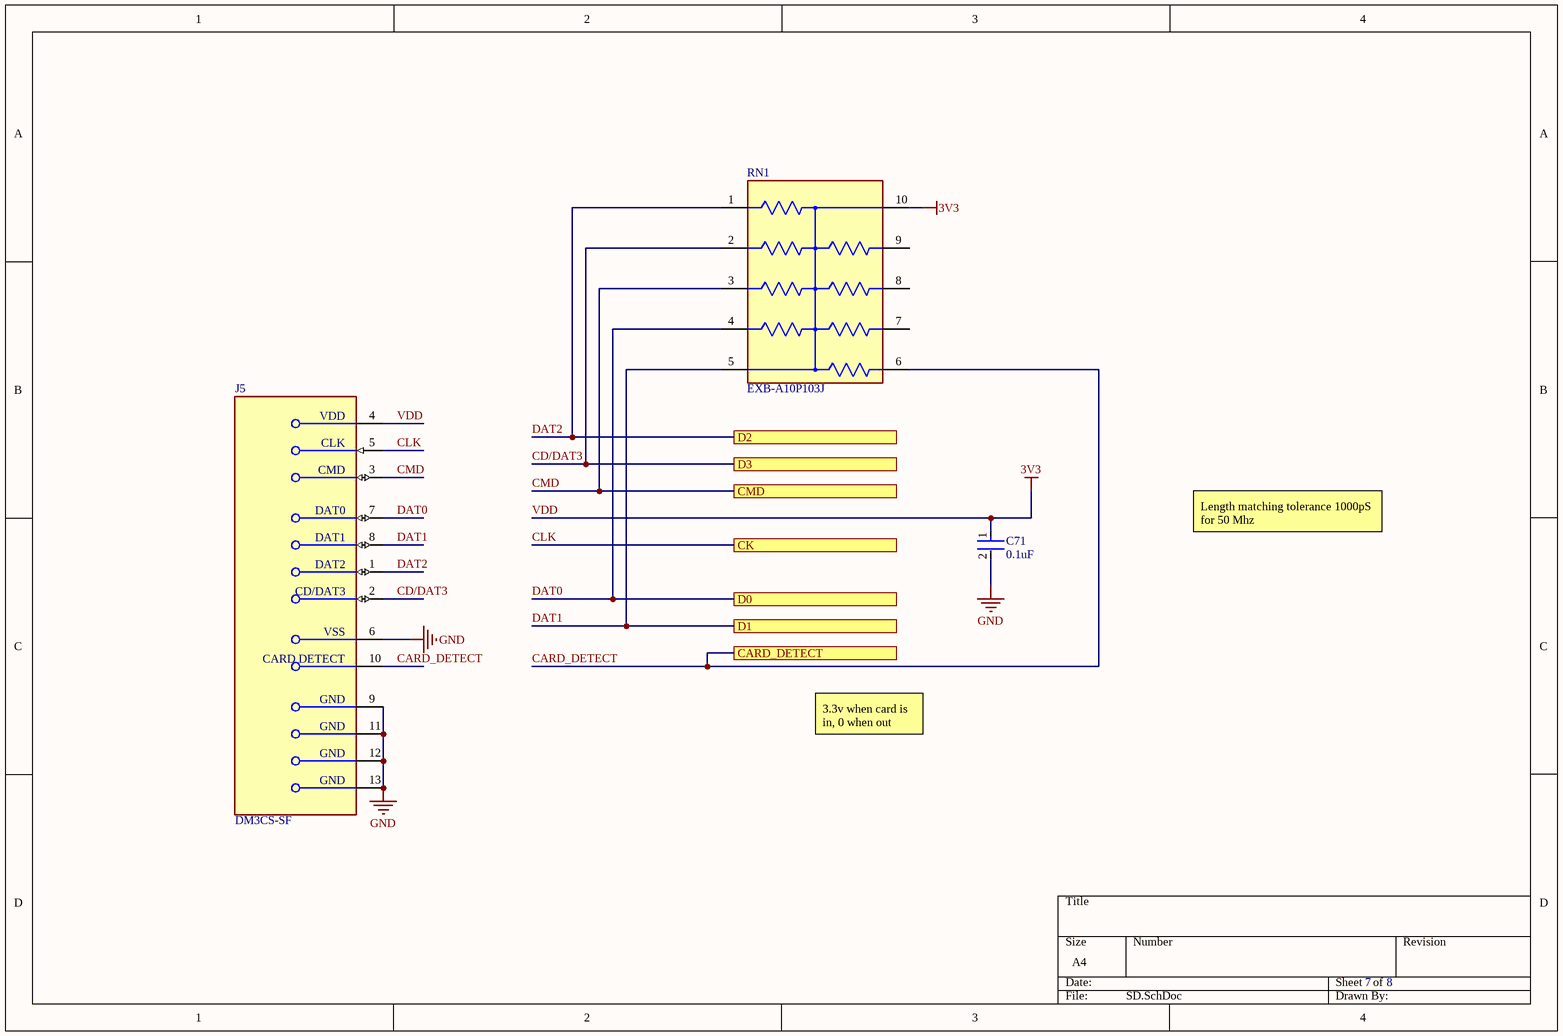
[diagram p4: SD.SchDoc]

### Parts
C71  0.1uF  [FP-CL10-IPC_C]
J5  DM3CS-SF  [FP-DM3CS-SF-MFG]
RN1  EXB-A10P103J  [FP-EXBA-MFG]

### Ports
CARD_DETECT, CK, CMD, D0, D1, D2, D3

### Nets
GND: C71.2 J5.6(VSS) J5.9(GND) J5.11(GND) J5.12(GND) J5.13(GND)
VDD: C71.1 J5.4(VDD) RN1.10  [also labelled 3V3]
CARD_DETECT: J5.10(CARD_DETECT) RN1.6 ; port CARD_DETECT
CD/DAT3: J5.2(CD/DAT3) RN1.2 ; port D3
CLK: J5.5(CLK) ; port CK
CMD: J5.3(CMD) RN1.3 ; port CMD
DAT0: J5.7(DAT0) RN1.4 ; port D0
DAT1: J5.8(DAT1) RN1.5 ; port D1
DAT2: J5.1(DAT2) RN1.1 ; port D2

Not connected (* = marked no-connect by the designer): RN1 7 8 9

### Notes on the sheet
- Length matching tolerance 1000pS for 50 Mhz
- 3.3v when card is in, 0 when out
- 7
- 8

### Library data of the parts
C71 = CMP-13271-002683-1: as C1 on sheet MCU
J5 = CMP-11597-000003-1: CONN MICRO SD CARD HINGED TYPE; Pitch: 1.1mm; Connector Type: Connector; Current Rating: 500mA; Voltage Rating (AC): 125V; Gender: Female; Insulation Resistance: 1GR; Number of Positions: 8; Contact Resistance: 100mR
RN1 = CMP-00287-42270834-1: EXB-A10P103J Res Thick Film NET 10K Ohm 5% ±200ppm/℃ BUS Molded 10-Pin 2512 Concave SMD Embossed Carrier T/R; Resistance: 10kΩ; Number of Elements: 8; Power Dissipation: 63mW; Voltage Rating (DC): 100V; Voltage Rating: 50V; Circuit Type: Bussed; Power Per Element: 62.5mW; Number of Contacts: 10; Temperature Coefficient: 200ppm/°C

## Sheet Flash.SchDoc
size A4; SheetNumber: 6; SheetTotal: 8
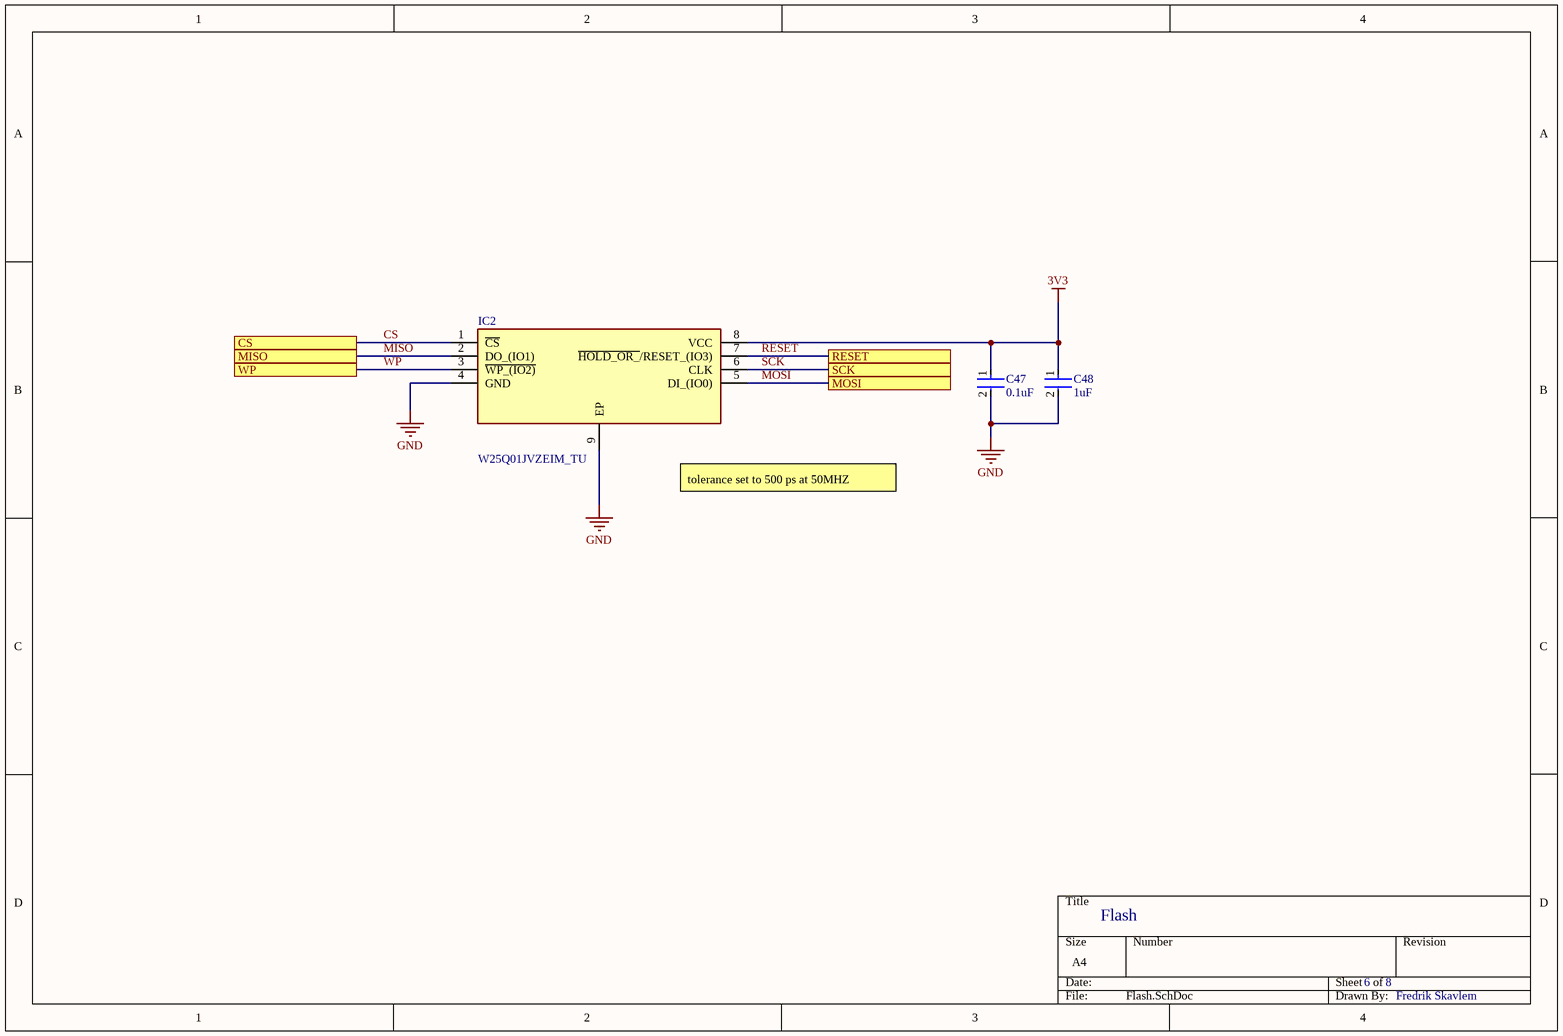
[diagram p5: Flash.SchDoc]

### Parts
C47  0.1uF  [FP-CL10-IPC_C]
C48  1uF  [FP-CL10-IPC_C]
IC2  W25Q01JVZEIM_TU  [SON127P800X600X80-9N-D]

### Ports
CS, MISO, MOSI, RESET, SCK, WP

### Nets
3V3: C47.1 C48.1 IC2.8(VCC)  [project net VDD]
GND: C47.2 C48.2 IC2.4(GND) IC2.9(EP)
CS: IC2.1(~{CS}) ; port CS
MISO: IC2.2(DO_(IO1)) ; port MISO
MOSI: IC2.5(DI_(IO0)) ; port MOSI
RESET: IC2.7(~{HOLD_OR_}/RESET_(IO3)) ; port RESET  [project net FLASH_RESET]
SCK: IC2.6(CLK) ; port SCK
WP: IC2.3(~{WP_(IO2)}) ; port WP  [project net FLASH_WP]

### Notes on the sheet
- (near IC2) tolerance set to 500 ps at 50MHZ
- Flash
- 6
- 8
- Fredrik Skavlem

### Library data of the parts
C47 = CMP-13271-002683-1: as C1 on sheet MCU
C48 = CMP-13271-000784-1: as C23 on sheet Power
IC2 = W25Q01JVZEIM_TU: Integrated Circuit; Manufacturer_Name: Winbond; Manufacturer_Part_Number: W25Q01JVZEIM TU

## Sheet AnalogMeas.SchDoc
size A4; SheetNumber: 8; SheetTotal: 8
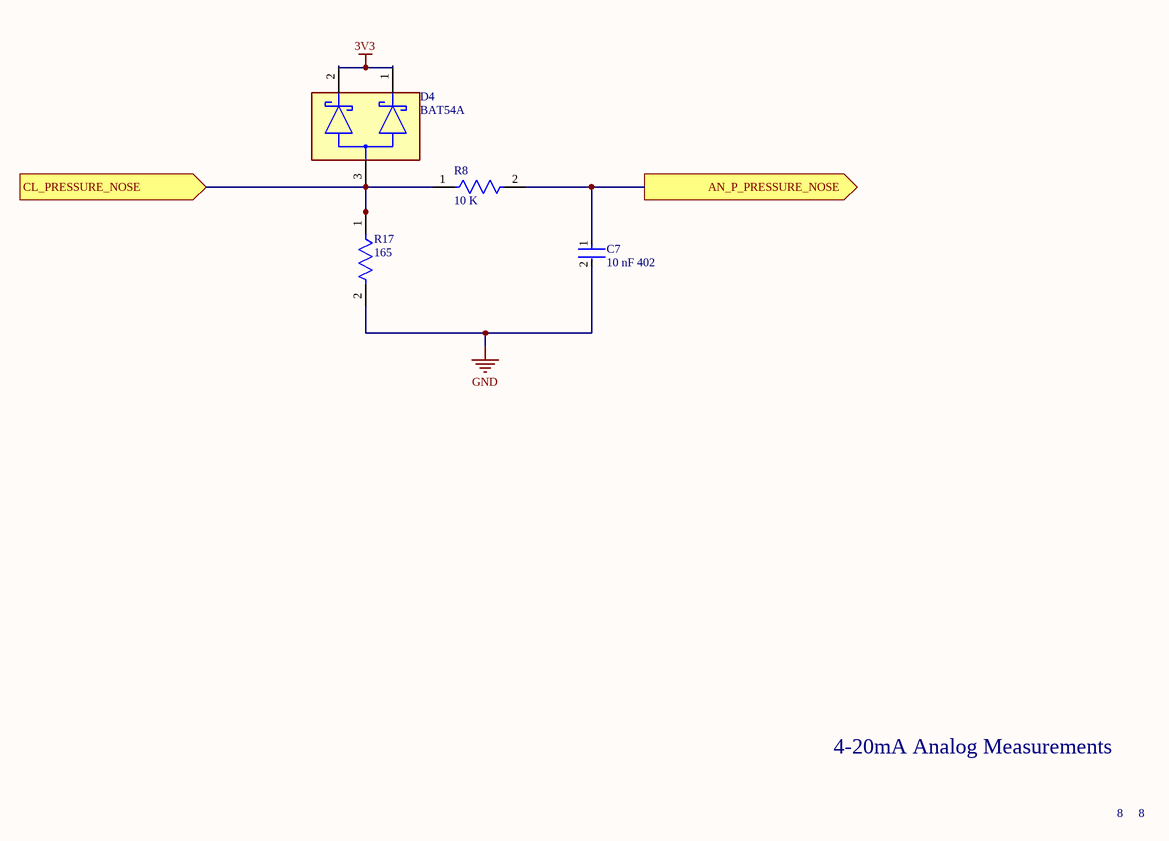
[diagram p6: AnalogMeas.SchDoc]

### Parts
C7  10 nF 402  [FP-GJM155-0_05-IPC_C]
D4  BAT54A  [FP-BAT54A-IPC_B]
R8  10 K  [FP-RP73P-1E-MFG]
R17  165  [FP-RP73P-1E-MFG]

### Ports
AN_P_PRESSURE_NOSE (out), CL_PRESSURE_NOSE (in)

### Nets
3V3: D4.1(1_CATHODE) D4.2(2_CATHODE)  [project net VDD]
GND: C7.2 R17.2
AN_P_PRESSURE_NOSE: C7.1 R8.2 ; port AN_P_PRESSURE_NOSE
CL_PRESSURE_NOSE: D4.3(COMMON_ANODE) R8.1 R17.1 ; port CL_PRESSURE_NOSE

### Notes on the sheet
- 4-20mA Analog Measurements
- 8

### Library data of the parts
C7 = CMP-2008-03910-2: Multi-Layer Ceramic Capacitor 0.75pF C0G  ±0.1pF 0402 Paper T/R; Voltage Rating: 50V
D4 = CMP-90577-000001-1: Schottky Diodes & Rectifiers SOT23CA.0.2A 30V Sch ottky; Capacitance: 10pF; Current Rating: 200mA; Forward Voltage: 1V
R8 R17 = CMP-03211-011177-1: RP73P 0402 165Ω 0.1W 25ppm/°C 0.10% 50V; Manufacturer Part Number: RP73PF1E165RBTD; Manufacturer: TE Connectivity

## Sheet USBC.SchDoc
size A4; SheetNumber: 3; SheetTotal: 8
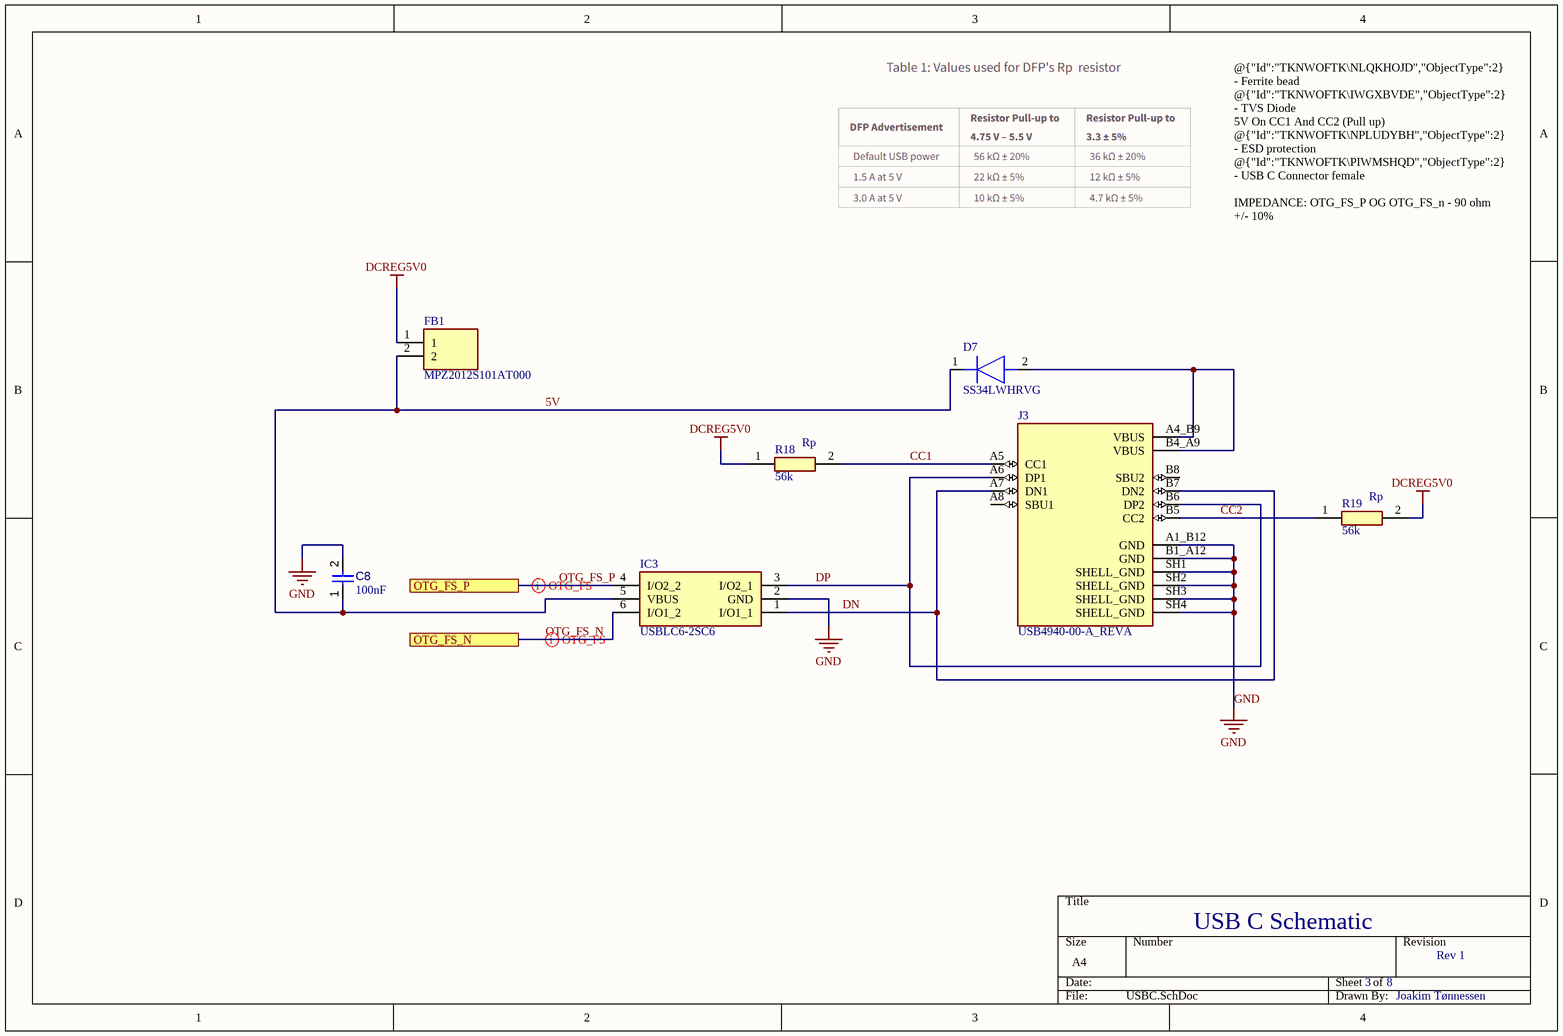
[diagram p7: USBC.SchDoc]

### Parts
C8  value 100nF  [CAPC2012X09N]  (hidden comment: 08053C104JAZ2A)
D7  SS34LWHRVG  [SODFL3718X102N]
FB1  MPZ2012S101AT000  [BEADC2012X105N]
IC3  USBLC6-2SC6  [SOT95P280X145-6N]
J3  USB4940-00-A_REVA  [GCT_USB4940-00-A_REVA]
R18  56k  [RESC1608X50N]
R19  56k  [RESC1608X50N]

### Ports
OTG_FS_N, OTG_FS_P

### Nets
DCREG5V0: FB1.1 R18.1 R19.2
GND: C8.2 IC3.2(GND) J3.A1_B12(GND) J3.B1_A12(GND) J3.SH1(SHELL_GND) J3.SH2(SHELL_GND) J3.SH3(SHELL_GND) J3.SH4(SHELL_GND)
5V: C8.1 D7.1(K) FB1.2 IC3.5(VBUS)
CC1: J3.A5(CC1) R18.2
CC2: J3.B5(CC2) R19.1
DN: IC3.1(I/O1_1) J3.A7(DN1) J3.B7(DN2)
DP: IC3.3(I/O2_1) J3.A6(DP1) J3.B6(DP2)
OTG_FS_N: IC3.6(I/O1_2) ; port OTG_FS_N
OTG_FS_P: IC3.4(I/O2_2) ; port OTG_FS_P
NetD7_2: D7.2(A) J3.A4_B9(VBUS) J3.B4_A9(VBUS)

Not connected (* = marked no-connect by the designer): J3 A8(SBU1) B8(SBU2)

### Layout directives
differential pair: OTG_FS_N, OTG_FS_P

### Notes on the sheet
- @{"Id":"TKNWOFTK\NLQKHOJD","ObjectType":2} - Ferrite bead
  @{"Id":"TKNWOFTK\IWGXBVDE","ObjectType":2} - TVS Diode
  5V On CC1 And CC2 (Pull up)
  @{"Id":"TKNWOFTK\NPLUDYBH","ObjectType":2} - ESD protection
  @{"Id":"TKNWOFTK\PIWMSHQD","ObjectType":2} - USB C Connector female
  IMPEDANCE: OTG_FS_P OG OTG_FS_n - 90 ohm +/- 10%
- (near R18) Rp
- (near R19) Rp
- USB C Schematic
- 3
- 8
- Rev 1
- Joakim Tønnessen

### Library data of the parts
C8 = CMP-001-00127-1: Cap Ceramic 0.1uF 25V X7R 5% SMD 0805 FlexiTerm 125°C Paper T/R
D7 = SS34LWHRVG: Diode; Manufacturer_Name: Taiwan Semiconductor
FB1 = MPZ2012S101AT000: Ferrite Bead; Manufacturer_Name: TDK
IC3 = USBLC6-2SC6: Integrated Circuit; Manufacturer_Name: STMicroelectronics
J3 = CMP-002-00134-1: Type C USB 2.0 Connector; MF: Global Connector Technology
R18 R19 = CRCW060356K0JNEA: Resistor / CRCW060356K0JNEA; Manufacturer_Name: Vishay

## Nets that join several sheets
DCREG5V0: Power (8 pins), USBC (FB1.1 R18.1 R19.2)
GND: TopLevel (5 pins), MCU (13 pins), Power (61 pins), CANTransceiver (10 pins), SD (6 pins), Flash (C47.2 C48.2 IC2.4 IC2.9), CANTransceiver2 (10 pins), AnalogMeas (C7.2 R17.2), USBC (8 pins)
VBAT: TopLevel (P1.1), Power (9 pins)
VDD: TopLevel (J1.3), MCU (D1.2 R1.1), Power (34 pins), CANTransceiver (C46_CANTransceiver.1 IC1_CANTransceiver.3), SD (C71.1 J5.4 RN1.10), Flash (C47.1 C48.1 IC2.8), CANTransceiver2 (C46_CANTransceiver2.1 IC1_CANTransceiver2.3), AnalogMeas (D4.1 D4.2)
ADC1_INP2: MCU (U1.49), Power (C36.1 D5.1 R12.1 R13.2)
AN_P_PRESSURE_NOSE: MCU (U1.28), AnalogMeas (C7.1 R8.2)
CARD_DETECT: MCU (U1.26), SD (J5.10 RN1.6)
CD/DAT3: MCU (U1.134), SD (J5.2 RN1.2)
CL_PRESSURE_NOSE: TopLevel (P1.2), AnalogMeas (D4.3 R8.1 R17.1)
CLK: MCU (U1.27), SD (J5.5)
CMD: MCU (U1.34), SD (J5.3 RN1.3)
CS: MCU (U1.3), Flash (IC2.1)
DAT0: MCU (U1.75), SD (J5.7 RN1.4)
DAT1: MCU (U1.76), SD (J5.8 RN1.5)
DAT2: MCU (U1.126), SD (J5.1 RN1.1)
FDCAN1_RX: MCU (U1.139), CANTransceiver (IC1_CANTransceiver.4)
FDCAN1_TX: MCU (U1.140), CANTransceiver (IC1_CANTransceiver.1)
FDCAN2_RX: MCU (U1.73), CANTransceiver2 (IC1_CANTransceiver2.4)
FDCAN2_TX: MCU (U1.74), CANTransceiver2 (IC1_CANTransceiver2.1)
FLASH_RESET: MCU (U1.57), Flash (IC2.7)
FLASH_WP: MCU (U1.56), Flash (IC2.3)
MISO: MCU (U1.4), Flash (IC2.2)
MOSI: MCU (U1.5), Flash (IC2.5)
OTG_FS_N: MCU (U1.103), USBC (IC3.6)
OTG_FS_P: MCU (U1.104), USBC (IC3.4)
SCK: MCU (U1.1), Flash (IC2.6)
T_JTDI: TopLevel (J1.10), MCU (U1.110)
T_NRST: TopLevel (J1.12), MCU (C1.1 U1.25)
T_SWCLK: TopLevel (J1.6), MCU (U1.109)
T_SWDIO: TopLevel (J1.4), MCU (U1.105)
T_SWO: TopLevel (J1.8), MCU (U1.133)
T_VCP_RX: TopLevel (J1.13), MCU (U1.78)
T_VCP_TX: TopLevel (J1.14), MCU (U1.77)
